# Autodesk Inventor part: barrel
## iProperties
Created: 2006-04
Part Number: barrel
Document SubType Name: Modeling
Designer: Калинин
Author: Калинин
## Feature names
1. Вращение1 [Revolution]
2. Пружина1
3. Круговой массив1 [Circular Pattern]
4. Фаска1 [Chamfer]
5. Фаска2 [Chamfer]
6. Выдавливание1 [Extrusion]
7. Выдавливание2 [Extrusion]
8. Сопряжение1 [Fillet]
9. Сопряжение2 [Fillet]
